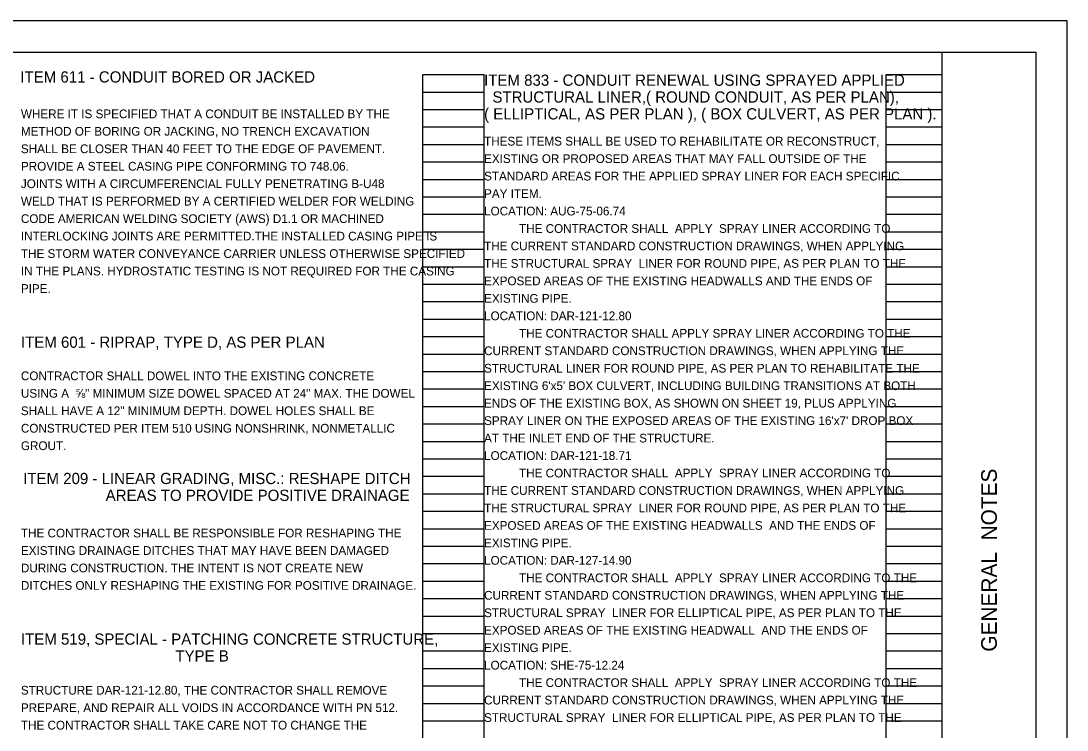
# Model space of a CAD drawing. Extents: x 0 to 34, y 0 to 22.
# Drawn here: x 17.24 to 34, y 10.63 to 22 of the extents above; entities that cross this region are included whole.
import ezdxf

# ---------------------------------------------------------------- set-up
doc = ezdxf.new("R2010")
doc.units = 0
for name, color, linetype in [('Default', 7, 'Continuous'), ('SH_Border', 7, 'Continuous'), ('SH_Cut_Line', 7, 'Continuous'), ('SH_Data', 7, 'Continuous'), ('SH_Text', 7, 'Continuous')]:
    doc.layers.add(name, color=color, linetype=linetype)

msp = doc.modelspace()

# ---------------------------------------------------------------- linework, layer by layer
at = {"layer": 'SH_Border'}
msp.add_line((32, 0.5), (32, 21.5), dxfattribs=at)
msp.add_lwpolyline([(1.5, 21.5), (33.5, 21.5), (33.5, 0.5), (1.5, 0.5)], close=True, dxfattribs=at)
at = {"layer": 'SH_Cut_Line'}
msp.add_lwpolyline([(0, 0), (34, 0), (34, 22), (0, 22)], close=True, dxfattribs=at)
at = {"layer": 'SH_Data'}
for p, q in [((23.68, 0.98), (23.68, 21.14)), ((23.68, 21.14), (24.66, 21.14)), ((24.66, 0.98), (24.66, 21.14)), ((31.1, 0.98), (31.1, 21.14)), ((31.1, 21.14), (32, 21.14)), ((32, 0.98), (32, 21.14)), ((23.68, 20.86), (24.66, 20.86)), ((31.1, 20.86), (32, 20.86)), ((23.68, 20.58), (24.66, 20.58)), ((31.1, 20.58), (32, 20.58)), ((23.68, 20.3), (24.66, 20.3)), ((31.1, 20.3), (32, 20.3)), ((23.68, 20.02), (24.66, 20.02)), ((31.1, 20.02), (32, 20.02)), ((23.68, 19.74), (24.66, 19.74)), ((31.1, 19.74), (32, 19.74)), ((23.68, 19.46), (24.66, 19.46)), ((31.1, 19.46), (32, 19.46)), ((23.68, 19.18), (24.66, 19.18)), ((31.1, 19.18), (32, 19.18)), ((23.68, 18.9), (24.66, 18.9)), ((31.1, 18.9), (32, 18.9)), ((23.68, 18.62), (24.66, 18.62)), ((31.1, 18.62), (32, 18.62)), ((23.68, 18.34), (24.66, 18.34)), ((31.1, 18.34), (32, 18.34)), ((23.68, 18.06), (24.66, 18.06)), ((31.1, 18.06), (32, 18.06)), ((23.68, 17.78), (24.66, 17.78)), ((31.1, 17.78), (32, 17.78)), ((23.68, 17.5), (24.66, 17.5)), ((31.1, 17.5), (32, 17.5)), ((23.68, 17.22), (24.66, 17.22)), ((31.1, 17.22), (32, 17.22)), ((23.68, 16.94), (24.66, 16.94)), ((31.1, 16.94), (32, 16.94)), ((23.68, 16.66), (24.66, 16.66)), ((31.1, 16.66), (32, 16.66)), ((23.68, 16.38), (24.66, 16.38)), ((31.1, 16.38), (32, 16.38)), ((23.68, 16.1), (24.66, 16.1)), ((31.1, 16.1), (32, 16.1)), ((23.68, 15.82), (24.66, 15.82)), ((31.1, 15.82), (32, 15.82)), ((23.68, 15.54), (24.66, 15.54)), ((31.1, 15.54), (32, 15.54)), ((23.68, 15.26), (24.66, 15.26)), ((31.1, 15.26), (32, 15.26)), ((23.68, 14.98), (24.66, 14.98)), ((31.1, 14.98), (32, 14.98)), ((23.68, 14.7), (24.66, 14.7)), ((31.1, 14.7), (32, 14.7)), ((23.68, 14.42), (24.66, 14.42)), ((31.1, 14.42), (32, 14.42)), ((23.68, 14.14), (24.66, 14.14)), ((31.1, 14.14), (32, 14.14)), ((23.68, 13.86), (24.66, 13.86)), ((31.1, 13.86), (32, 13.86)), ((23.68, 13.58), (24.66, 13.58)), ((31.1, 13.58), (32, 13.58)), ((23.68, 13.3), (24.66, 13.3)), ((31.1, 13.3), (32, 13.3)), ((23.68, 13.02), (24.66, 13.02)), ((31.1, 13.02), (32, 13.02)), ((23.68, 12.74), (24.66, 12.74)), ((31.1, 12.74), (32, 12.74)), ((23.68, 12.46), (24.66, 12.46)), ((31.1, 12.46), (32, 12.46)), ((23.68, 12.18), (24.66, 12.18)), ((31.1, 12.18), (32, 12.18)), ((23.68, 11.9), (24.66, 11.9)), ((31.1, 11.9), (32, 11.9)), ((23.68, 11.62), (24.66, 11.62)), ((31.1, 11.62), (32, 11.62)), ((23.68, 11.34), (24.66, 11.34)), ((31.1, 11.34), (32, 11.34)), ((23.68, 11.06), (24.66, 11.06)), ((31.1, 11.06), (32, 11.06)), ((23.68, 10.78), (24.66, 10.78)), ((31.1, 10.78), (32, 10.78))]:
    msp.add_line(p, q, dxfattribs=at)

# ---------------------------------------------------------------- texts
at = {"layer": 'Default'}
for s, height, p in [('ITEM 833 - CONDUIT RENEWAL USING SPRAYED APPLIED ', 0.18, (24.66, 20.96)), ('  STRUCTURAL LINER,( ROUND CONDUIT, AS PER PLAN),', 0.18, (24.66, 20.69)), ('( ELLIPTICAL, AS PER PLAN ), ( BOX CULVERT, AS PER PLAN ).', 0.18, (24.66, 20.42)), ('THESE ITEMS SHALL BE USED TO REHABILITATE OR RECONSTRUCT,', 0.14, (24.66, 20.002)), ('EXISTING OR PROPOSED AREAS THAT MAY FALL OUTSIDE OF THE', 0.14, (24.66, 19.722)), ('STANDARD AREAS FOR THE APPLIED SPRAY LINER FOR EACH SPECIFIC', 0.14, (24.66, 19.442)), ('PAY ITEM.', 0.14, (24.66, 19.162)), ('LOCATION: AUG-75-06.74', 0.14, (24.66, 18.882)), ('THE CONTRACTOR SHALL  APPLY  SPRAY LINER ACCORDING TO ', 0.14, (25.22, 18.602)), ('THE CURRENT STANDARD CONSTRUCTION DRAWINGS, WHEN APPLYING', 0.14, (24.66, 18.322)), ('THE STRUCTURAL SPRAY  LINER FOR ROUND PIPE, AS PER PLAN TO THE ', 0.14, (24.66, 18.042)), ('EXPOSED AREAS OF THE EXISTING HEADWALLS AND THE ENDS OF ', 0.14, (24.66, 17.762)), ('EXISTING PIPE. ', 0.14, (24.66, 17.482)), ('LOCATION: DAR-121-12.80', 0.14, (24.66, 17.202)), ('THE CONTRACTOR SHALL APPLY SPRAY LINER ACCORDING TO THE', 0.14, (25.22, 16.922)), ('CURRENT STANDARD CONSTRUCTION DRAWINGS, WHEN APPLYING THE ', 0.14, (24.66, 16.642)), ('STRUCTURAL LINER FOR ROUND PIPE, AS PER PLAN TO REHABILITATE THE ', 0.14, (24.66, 16.362)), ('CONTRACTOR SHALL DOWEL INTO THE EXISTING CONCRETE ', 0.14, (17.24, 16.24)), ('USING A  ⅝" MINIMUM SIZE DOWEL SPACED AT 24" MAX. THE DOWEL ', 0.14, (17.24, 15.96)), ("EXISTING 6'x5' BOX CULVERT, INCLUDING BUILDING TRANSITIONS AT BOTH ", 0.14, (24.66, 16.082)), ('ENDS OF THE EXISTING BOX, AS SHOWN ON SHEET 19, PLUS APPLYING', 0.14, (24.66, 15.802)), ('SHALL HAVE A 12" MINIMUM DEPTH. DOWEL HOLES SHALL BE ', 0.14, (17.24, 15.68)), ("SPRAY LINER ON THE EXPOSED AREAS OF THE EXISTING 16'x7' DROP BOX ", 0.14, (24.66, 15.522)), ('CONSTRUCTED PER ITEM 510 USING NONSHRINK, NONMETALLIC ', 0.14, (17.24, 15.4)), ('GROUT.', 0.14, (17.24, 15.12)), ('AT THE INLET END OF THE STRUCTURE.  ', 0.14, (24.66, 15.242)), ('LOCATION: DAR-121-18.71', 0.14, (24.66, 14.962)), ('THE CONTRACTOR SHALL  APPLY  SPRAY LINER ACCORDING TO ', 0.14, (25.22, 14.682)), ('THE CURRENT STANDARD CONSTRUCTION DRAWINGS, WHEN APPLYING', 0.14, (24.66, 14.402)), ('THE STRUCTURAL SPRAY  LINER FOR ROUND PIPE, AS PER PLAN TO THE ', 0.14, (24.66, 14.122)), ('EXPOSED AREAS OF THE EXISTING HEADWALLS  AND THE ENDS OF ', 0.14, (24.66, 13.842)), ('THE CONTRACTOR SHALL BE RESPONSIBLE FOR RESHAPING THE ', 0.14, (17.24, 13.72)), ('EXISTING DRAINAGE DITCHES THAT MAY HAVE BEEN DAMAGED ', 0.14, (17.24, 13.44)), ('EXISTING PIPE.', 0.14, (24.66, 13.562)), ('LOCATION: DAR-127-14.90', 0.14, (24.66, 13.282)), ('DURING CONSTRUCTION. THE INTENT IS NOT CREATE NEW ', 0.14, (17.24, 13.16)), ('THE CONTRACTOR SHALL  APPLY  SPRAY LINER ACCORDING TO THE', 0.14, (25.22, 13.002)), ('DITCHES ONLY RESHAPING THE EXISTING FOR POSITIVE DRAINAGE.', 0.14, (17.24, 12.88)), ('CURRENT STANDARD CONSTRUCTION DRAWINGS, WHEN APPLYING THE ', 0.14, (24.66, 12.722)), ('STRUCTURAL SPRAY  LINER FOR ELLIPTICAL PIPE, AS PER PLAN TO THE ', 0.14, (24.66, 12.442)), ('EXPOSED AREAS OF THE EXISTING HEADWALL  AND THE ENDS OF ', 0.14, (24.66, 12.162)), ('EXISTING PIPE.', 0.14, (24.66, 11.882)), ('LOCATION: SHE-75-12.24', 0.14, (24.66, 11.602)), ('THE CONTRACTOR SHALL  APPLY  SPRAY LINER ACCORDING TO THE', 0.14, (25.22, 11.322)), ('CURRENT STANDARD CONSTRUCTION DRAWINGS, WHEN APPLYING THE ', 0.14, (24.66, 11.042)), ('STRUCTURAL SPRAY  LINER FOR ELLIPTICAL PIPE, AS PER PLAN TO THE ', 0.14, (24.66, 10.762))]:
    msp.add_text(s, height=height, dxfattribs=at).set_placement(p)
at = {"layer": 'SH_Data'}
msp.add_text('GENERAL  NOTES', height=0.25, rotation=90, dxfattribs=at).set_placement((32.875, 11.888))
at = {"layer": 'SH_Text'}
for s, height, p in [('ITEM 611 - CONDUIT BORED OR JACKED', 0.18, (17.231, 21.012)), ('WHERE IT IS SPECIFIED THAT A CONDUIT BE INSTALLED BY THE', 0.14, (17.24, 20.44)), ('METHOD OF BORING OR JACKING, NO TRENCH EXCAVATION', 0.14, (17.24, 20.16)), ('SHALL BE CLOSER THAN 40 FEET TO THE EDGE OF PAVEMENT.', 0.14, (17.24, 19.88)), ('PROVIDE A STEEL CASING PIPE CONFORMING TO 748.06.', 0.14, (17.24, 19.6)), ('JOINTS WITH A CIRCUMFERENCIAL FULLY PENETRATING B-U48', 0.14, (17.24, 19.32)), ('WELD THAT IS PERFORMED BY A CERTIFIED WELDER FOR WELDING', 0.14, (17.24, 19.04)), ('CODE AMERICAN WELDING SOCIETY (AWS) D1.1 OR MACHINED ', 0.14, (17.24, 18.76)), ('INTERLOCKING JOINTS ARE PERMITTED.THE INSTALLED CASING PIPE IS ', 0.14, (17.24, 18.48)), ('THE STORM WATER CONVEYANCE CARRIER UNLESS OTHERWISE SPECIFIED ', 0.14, (17.24, 18.2)), ('IN THE PLANS. HYDROSTATIC TESTING IS NOT REQUIRED FOR THE CASING ', 0.14, (17.24, 17.92)), ('PIPE.', 0.14, (17.24, 17.64)), ('ITEM 601 - RIPRAP, TYPE D, AS PER PLAN', 0.18, (17.24, 16.76)), ('ITEM 209 - LINEAR GRADING, MISC.: RESHAPE DITCH ', 0.18, (17.276, 14.575)), ('         AREAS TO PROVIDE POSITIVE DRAINAGE', 0.18, (17.996, 14.305)), ('ITEM 519, SPECIAL - PATCHING CONCRETE STRUCTURE, ', 0.18, (17.24, 12)), ('                                     TYPE B', 0.18, (17.24, 11.73)), ('STRUCTURE DAR-121-12.80, THE CONTRACTOR SHALL REMOVE  ', 0.14, (17.24, 11.2)), ('PREPARE, AND REPAIR ALL VOIDS IN ACCORDANCE WITH PN 512. ', 0.14, (17.24, 10.92)), ('THE CONTRACTOR SHALL TAKE CARE NOT TO CHANGE THE', 0.14, (17.24, 10.64))]:
    msp.add_text(s, height=height, dxfattribs=at).set_placement(p)

doc.saveas('drawing.dxf')
